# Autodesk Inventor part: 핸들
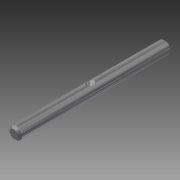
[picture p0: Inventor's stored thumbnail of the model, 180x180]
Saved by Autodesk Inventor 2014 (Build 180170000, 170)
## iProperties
Created: 2019-04
Part Number: 핸들
Material: 스테인리스강
Document SubType Name: Modeling
Designer: mduedu
Density: 1 g/cm^3
Appearance: 반광택
Author: mduedu
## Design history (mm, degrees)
sketch "스케치1"
  geometry: C1 r 3 at (0, 0); 1 further point
  constraints: 1 centre point, 1 coincident
  dimensions: "d0" = 6 diameter of C1
extrude "돌출1" new body sketch "스케치1" stored distance "d1" = 74; taper "d2" = 0 deg
chamfer "모따기1" distance "d3" = 1; stored, may be unused: second distance "d4" = 2, angle "d5" = 45 deg
sketch "스케치2"
  geometry: L1 (-36, 3)-(36, 3) reference; L2 (0, 3)-(0, 1); L3 (0, 1)-(2, 3); L4 (0, 3)-(2, 3); 1 further point
  constraints: 6 end point, 2 perpendicular, 1 midpoint, 1 point on line
  dimensions: "d6" = 4 diameter of L3.end L2; "d8" = 45 deg angle of L3 L2
revolve "회전1" sketch "스케치2" stored, may be unused: angle "d10" = 90 deg
node "작업점1"
  node "작업축1"
  node "작업 평면1"
workaxis "Work Axis2"
sketch "Sketch3"
  geometry: L1 (-36, 3)-(36, 3) reference; L2 (-2, 3)-(2, 3); L3 (-2, 3)-(0, 1); L4 (-2, 3)-(0.828, 3); L5 (0, 1)-(2, 3); 2 further points
  constraints: 8 end point, 2 midpoint, 1 collinear, 1 equal length, 1 horizontal, 1 perpendicular
  dimensions: "d11" = 4 distance of L2.start L2.end; "d12" = 45 deg angle of L3 L4
workpoint "Work Point2"
node "솔리드1"
